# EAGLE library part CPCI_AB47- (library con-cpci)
Compact PCI A+B 47 Monoblock Source: www.erni.com
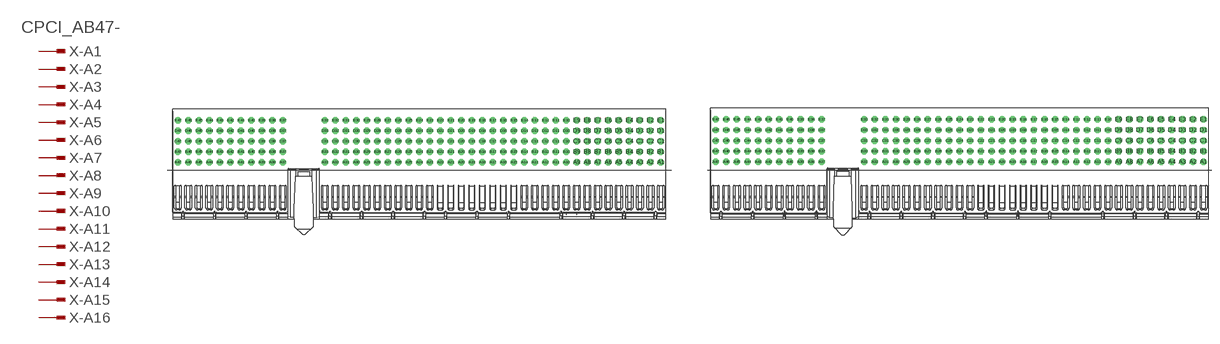
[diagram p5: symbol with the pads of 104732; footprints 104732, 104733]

Designator prefix X; gates -A1=PINV -A2=PIN -A3=PIN -A4=PIN -A5=PIN -A6=PIN -A7=PIN -A8=PIN -A9=PIN -A10=PIN -A11=PIN -A12=PIN -A13=PIN -A14=PIN -A15=PIN -A16=PIN -A17=PIN -A18=PIN -A19=PIN -A20=PIN -A21=PIN -A22=PIN -A23=PIN -A24=PIN -A25=PIN -A26=PIN -A27=PIN -A28=PIN -A29=PIN -A30=PIN -A31=PIN -A32=PIN -A33=PIN -A37=PIN -A38=PIN -A39=PIN -A40=PIN -A41=PIN -A42=PIN -A43=PIN -A44=PIN -A45=PIN -A46=PIN -A47=PIN -B1=PINV -C1=PINV -D1=PINV -E1=PINV -B2=PIN -B3=PIN -B4=PIN -B5=PIN -B6=PIN -B7=PIN -B8=PIN -B9=PIN -B10=PIN -B11=PIN -B12=PIN -B13=PIN -B14=PIN -B15=PIN -B16=PIN -B17=PIN -B18=PIN -B19=PIN -B20=PIN -B21=PIN -B22=PIN -B23=PIN -B24=PIN -B25=PIN -B26=PIN -B27=PIN -B28=PIN -B29=PIN -B30=PIN -B31=PIN -B32=PIN -B33=PIN -B37=PIN -B38=PIN -B39=PIN -B40=PIN -B41=PIN -B42=PIN -B43=PIN -B44=PIN -B45=PIN -B46=PIN -B47=PIN -C2=PIN -C3=PIN -C4=PIN -C5=PIN -C6=PIN -C7=PIN -C8=PIN -C9=PIN -C10=PIN -C11=PIN -C12=PIN -C13=PIN -C14=PIN -C15=PIN -C16=PIN -C17=PIN -C18=PIN -C19=PIN -C20=PIN -C21=PIN -C22=PIN -C23=PIN -C24=PIN -C25=PIN -C26=PIN -C27=PIN -C28=PIN -C29=PIN -C30=PIN -C31=PIN -C32=PIN -C33=PIN -C37=PIN -C38=PIN -C39=PIN -C40=PIN -C41=PIN -C42=PIN -C43=PIN -C44=PIN -C45=PIN -C46=PIN -C47=PIN -D2=PIN -D3=PIN -D4=PIN -D5=PIN -D6=PIN -D7=PIN -D8=PIN -D9=PIN -D10=PIN -D11=PIN -D12=PIN -D13=PIN -D14=PIN -D15=PIN -D16=PIN -D17=PIN -D18=PIN -D19=PIN -D20=PIN -D21=PIN -D22=PIN -D23=PIN -D24=PIN -D25=PIN -D26=PIN -D27=PIN -D28=PIN -D29=PIN -D30=PIN -D31=PIN -D32=PIN -D33=PIN -D37=PIN -D38=PIN -D39=PIN -D40=PIN -D41=PIN -D42=PIN -D43=PIN -D44=PIN -D45=PIN -D46=PIN -D47=PIN -E2=PIN -E3=PIN -E4=PIN -E5=PIN -E6=PIN -E7=PIN -E8=PIN -E9=PIN -E10=PIN -E11=PIN -E12=PIN -E13=PIN -E14=PIN -E15=PIN -E16=PIN -E17=PIN -E18=PIN -E19=PIN -E20=PIN -E21=PIN -E22=PIN -E23=PIN -E24=PIN -E25=PIN -E26=PIN -E27=PIN -E28=PIN -E29=PIN -E30=PIN -E31=PIN -E32=PIN -E33=PIN -E37=PIN -E38=PIN -E39=PIN -E40=PIN -E41=PIN -E42=PIN -E43=PIN -E44=PIN -E45=PIN -E46=PIN -E47=PIN

## CPCI_AB47-104732  [104732]
A1  -A1:1  in
A2  -A2:1  in
A3  -A3:1  in
A4  -A4:1  in
A5  -A5:1  in
A6  -A6:1  in
A7  -A7:1  in
A8  -A8:1  in
A9  -A9:1  in
A10  -A10:1  in
A11  -A11:1  in
A12  -A12:1  in
A13  -A13:1  in
A14  -A14:1  in
A15  -A15:1  in
A16  -A16:1  in
A17  -A17:1  in
A18  -A18:1  in
A19  -A19:1  in
A20  -A20:1  in
A21  -A21:1  in
A22  -A22:1  in
A23  -A23:1  in
A24  -A24:1  in
A25  -A25:1  in
A26  -A26:1  in
A27  -A27:1  in
A28  -A28:1  in
A29  -A29:1  in
A30  -A30:1  in
A31  -A31:1  in
A32  -A32:1  in
A33  -A33:1  in
A37  -A37:1  in
A38  -A38:1  in
A39  -A39:1  in
A40  -A40:1  in
A41  -A41:1  in
A42  -A42:1  in
A43  -A43:1  in
A44  -A44:1  in
A45  -A45:1  in
A46  -A46:1  in
A47  -A47:1  in
B1  -B1:1  in
B2  -B2:1  in
B3  -B3:1  in
B4  -B4:1  in
B5  -B5:1  in
B6  -B6:1  in
B7  -B7:1  in
B8  -B8:1  in
B9  -B9:1  in
B10  -B10:1  in
B11  -B11:1  in
B12  -B12:1  in
B13  -B13:1  in
B14  -B14:1  in
B15  -B15:1  in
B16  -B16:1  in
B17  -B17:1  in
B18  -B18:1  in
B19  -B19:1  in
B20  -B20:1  in
B21  -B21:1  in
B22  -B22:1  in
B23  -B23:1  in
B24  -B24:1  in
B25  -B25:1  in
B26  -B26:1  in
B27  -B27:1  in
B28  -B28:1  in
B29  -B29:1  in
B30  -B30:1  in
B31  -B31:1  in
B32  -B32:1  in
B33  -B33:1  in
B37  -B37:1  in
B38  -B38:1  in
B39  -B39:1  in
B40  -B40:1  in
B41  -B41:1  in
B42  -B42:1  in
B43  -B43:1  in
B44  -B44:1  in
B45  -B45:1  in
B46  -B46:1  in
B47  -B47:1  in
C1  -C1:1  in
C2  -C2:1  in
C3  -C3:1  in
C4  -C4:1  in
C5  -C5:1  in
C6  -C6:1  in
C7  -C7:1  in
C8  -C8:1  in
C9  -C9:1  in
C10  -C10:1  in
C11  -C11:1  in
C12  -C12:1  in
C13  -C13:1  in
C14  -C14:1  in
C15  -C15:1  in
C16  -C16:1  in
C17  -C17:1  in
C18  -C18:1  in
C19  -C19:1  in
C20  -C20:1  in
C21  -C21:1  in
C22  -C22:1  in
C23  -C23:1  in
C24  -C24:1  in
C25  -C25:1  in
C26  -C26:1  in
C27  -C27:1  in
C28  -C28:1  in
C29  -C29:1  in
C30  -C30:1  in
C31  -C31:1  in
C32  -C32:1  in
C33  -C33:1  in
C37  -C37:1  in
C38  -C38:1  in
C39  -C39:1  in
C40  -C40:1  in
C41  -C41:1  in
C42  -C42:1  in
C43  -C43:1  in
C44  -C44:1  in
C45  -C45:1  in
C46  -C46:1  in
C47  -C47:1  in
D1  -D1:1  in
D2  -D2:1  in
D3  -D3:1  in
D4  -D4:1  in
D5  -D5:1  in
D6  -D6:1  in
D7  -D7:1  in
D8  -D8:1  in
D9  -D9:1  in
D10  -D10:1  in
D11  -D11:1  in
D12  -D12:1  in
D13  -D13:1  in
D14  -D14:1  in
D15  -D15:1  in
D16  -D16:1  in
D17  -D17:1  in
D18  -D18:1  in
D19  -D19:1  in
D20  -D20:1  in
D21  -D21:1  in
D22  -D22:1  in
D23  -D23:1  in
D24  -D24:1  in
D25  -D25:1  in
D26  -D26:1  in
D27  -D27:1  in
D28  -D28:1  in
D29  -D29:1  in
D30  -D30:1  in
D31  -D31:1  in
D32  -D32:1  in
D33  -D33:1  in
D37  -D37:1  in
D38  -D38:1  in
D39  -D39:1  in
D40  -D40:1  in
D41  -D41:1  in
D42  -D42:1  in
D43  -D43:1  in
D44  -D44:1  in
D45  -D45:1  in
D46  -D46:1  in
D47  -D47:1  in
E1  -E1:1  in
E2  -E2:1  in
E3  -E3:1  in
E4  -E4:1  in
E5  -E5:1  in
E6  -E6:1  in
E7  -E7:1  in
E8  -E8:1  in
E9  -E9:1  in
E10  -E10:1  in
E11  -E11:1  in
E12  -E12:1  in
E13  -E13:1  in
E14  -E14:1  in
E15  -E15:1  in
E16  -E16:1  in
E17  -E17:1  in
E18  -E18:1  in
E19  -E19:1  in
E20  -E20:1  in
E21  -E21:1  in
E22  -E22:1  in
E23  -E23:1  in
E24  -E24:1  in
E25  -E25:1  in
E26  -E26:1  in
E27  -E27:1  in
E28  -E28:1  in
E29  -E29:1  in
E30  -E30:1  in
E31  -E31:1  in
E32  -E32:1  in
E33  -E33:1  in
E37  -E37:1  in
E38  -E38:1  in
E39  -E39:1  in
E40  -E40:1  in
E41  -E41:1  in
E42  -E42:1  in
E43  -E43:1  in
E44  -E44:1  in
E45  -E45:1  in
E46  -E46:1  in
E47  -E47:1  in

## CPCI_AB47-104733  [104733]
Pads as for 104732

## CPCI_AB47-104734  [104734]
Pads as for 104732

## CPCI_AB47-6U_AB47  [CPCI_6U_AB47]
Pads as for 104732

## CPCI_AB47-3U_AB47  [CPCI_3U_AB47]
Pads as for 104732

## Footprint 104732 (pad centres in mm)
ERmet Federleiste A+B 47 Monoblock Source: http://www.erni.com/DB/PDF-Drawing/ERmet/104732.pdf
drill 0.7 pad 1.016 octagon: A1 46,1.5; A2 44,1.5; A3 42,1.5; A4 40,1.5; A5 38,1.5; A6 36,1.5; A7 34,1.5; A8 32,1.5; A9 30,1.5; A10 28,1.5; A11 26,1.5; A12 24,1.5; A13 22,1.5; A14 20,1.5; A15 18,1.5; A16 16,1.5; A17 14,1.5; A18 12,1.5; A19 10,1.5; A20 8,1.5; A21 6,1.5; A22 4,1.5; A23 2,1.5; A24 0,1.5; A25 -2,1.5; A26 -4,1.5; A27 -6,1.5; A28 -8,1.5; A29 -10,1.5; A30 -12,1.5; A31 -14,1.5; A32 -16,1.5; A33 -18,1.5; A37 -26,1.5; A38 -28,1.5; A39 -30,1.5; A40 -32,1.5; A41 -34,1.5; A42 -36,1.5; A43 -38,1.5; A44 -40,1.5; A45 -42,1.5; A46 -44,1.5; A47 -46,1.5; B1 46,3.5; B2 44,3.5; B3 42,3.5; B4 40,3.5; B5 38,3.5; B6 36,3.5; B7 34,3.5; B8 32,3.5; B9 30,3.5; B10 28,3.5; B11 26,3.5; B12 24,3.5; B13 22,3.5; B14 20,3.5; B15 18,3.5; B16 16,3.5; B17 14,3.5; B18 12,3.5; B19 10,3.5; B20 8,3.5; B21 6,3.5; B22 4,3.5; B23 2,3.5; B24 0,3.5; B25 -2,3.5; B26 -4,3.5; B27 -6,3.5; B28 -8,3.5; B29 -10,3.5; B30 -12,3.5; B31 -14,3.5; B32 -16,3.5; B33 -18,3.5; B37 -26,3.5; B38 -28,3.5; B39 -30,3.5; B40 -32,3.5; B41 -34,3.5; B42 -36,3.5; B43 -38,3.5; B44 -40,3.5; B45 -42,3.5; B46 -44,3.5; B47 -46,3.5; C1 46,5.5; C2 44,5.5; C3 42,5.5; C4 40,5.5; C5 38,5.5; C6 36,5.5; C7 34,5.5; C8 32,5.5; C9 30,5.5; C10 28,5.5; C11 26,5.5; C12 24,5.5; C13 22,5.5; C14 20,5.5; C15 18,5.5; C16 16,5.5; C17 14,5.5; C18 12,5.5; C19 10,5.5; C20 8,5.5; C21 6,5.5; C22 4,5.5; C23 2,5.5; C24 0,5.5; C25 -2,5.5; C26 -4,5.5; C27 -6,5.5; C28 -8,5.5; C29 -10,5.5; C30 -12,5.5; C31 -14,5.5; C32 -16,5.5; C33 -18,5.5; C37 -26,5.5; C38 -28,5.5; C39 -30,5.5; C40 -32,5.5; C41 -34,5.5; C42 -36,5.5; C43 -38,5.5; C44 -40,5.5; C45 -42,5.5; C46 -44,5.5; C47 -46,5.5; D1 46,7.5; D2 44,7.5; D3 42,7.5; D4 40,7.5; D5 38,7.5; D6 36,7.5; D7 34,7.5; D8 32,7.5; D9 30,7.5; D10 28,7.5; D11 26,7.5; D12 24,7.5; D13 22,7.5; D14 20,7.5; D15 18,7.5; D16 16,7.5; D17 14,7.5; D18 12,7.5; D19 10,7.5; D20 8,7.5; D21 6,7.5; D22 4,7.5; D23 2,7.5; D24 0,7.5; D25 -2,7.5; D26 -4,7.5; D27 -6,7.5; D28 -8,7.5; D29 -10,7.5; D30 -12,7.5; D31 -14,7.5; D32 -16,7.5; D33 -18,7.5; D37 -26,7.5; D38 -28,7.5; D39 -30,7.5; D40 -32,7.5; D41 -34,7.5; D42 -36,7.5; D43 -38,7.5; D44 -40,7.5; D45 -42,7.5; D46 -44,7.5; D47 -46,7.5; E1 46,9.5; E2 44,9.5; E3 42,9.5; E4 40,9.5; E5 38,9.5; E6 36,9.5; E7 34,9.5; E8 32,9.5; E9 30,9.5; E10 28,9.5; E11 26,9.5; E12 24,9.5; E13 22,9.5; E14 20,9.5; E15 18,9.5; E16 16,9.5; E17 14,9.5; E18 12,9.5; E19 10,9.5; E20 8,9.5; E21 6,9.5; E22 4,9.5; E23 2,9.5; E24 0,9.5; E25 -2,9.5; E26 -4,9.5; E27 -6,9.5; E28 -8,9.5; E29 -10,9.5; E30 -12,9.5; E31 -14,9.5; E32 -16,9.5; E33 -18,9.5; E37 -26,9.5; E38 -28,9.5; E39 -30,9.5; E40 -32,9.5; E41 -34,9.5; E42 -36,9.5; E43 -38,9.5; E44 -40,9.5; E45 -42,9.5; E46 -44,9.5; E47 -46,9.5

## Footprint 104733 (pad centres in mm)
ERmet Federleiste A+B 47 Monoblock 3.3V/gelb Source: http://www.erni.com/DB/PDF-Drawing/ERmet/104733.pdf
drill 0.7 pad 1.016 octagon: A1 46,1.5; A2 44,1.5; A3 42,1.5; A4 40,1.5; A5 38,1.5; A6 36,1.5; A7 34,1.5; A8 32,1.5; A9 30,1.5; A10 28,1.5; A11 26,1.5; A12 24,1.5; A13 22,1.5; A14 20,1.5; A15 18,1.5; A16 16,1.5; A17 14,1.5; A18 12,1.5; A19 10,1.5; A20 8,1.5; A21 6,1.5; A22 4,1.5; A23 2,1.5; A24 0,1.5; A25 -2,1.5; A26 -4,1.5; A27 -6,1.5; A28 -8,1.5; A29 -10,1.5; A30 -12,1.5; A31 -14,1.5; A32 -16,1.5; A33 -18,1.5; A37 -26,1.5; A38 -28,1.5; A39 -30,1.5; A40 -32,1.5; A41 -34,1.5; A42 -36,1.5; A43 -38,1.5; A44 -40,1.5; A45 -42,1.5; A46 -44,1.5; A47 -46,1.5; B1 46,3.5; B2 44,3.5; B3 42,3.5; B4 40,3.5; B5 38,3.5; B6 36,3.5; B7 34,3.5; B8 32,3.5; B9 30,3.5; B10 28,3.5; B11 26,3.5; B12 24,3.5; B13 22,3.5; B14 20,3.5; B15 18,3.5; B16 16,3.5; B17 14,3.5; B18 12,3.5; B19 10,3.5; B20 8,3.5; B21 6,3.5; B22 4,3.5; B23 2,3.5; B24 0,3.5; B25 -2,3.5; B26 -4,3.5; B27 -6,3.5; B28 -8,3.5; B29 -10,3.5; B30 -12,3.5; B31 -14,3.5; B32 -16,3.5; B33 -18,3.5; B37 -26,3.5; B38 -28,3.5; B39 -30,3.5; B40 -32,3.5; B41 -34,3.5; B42 -36,3.5; B43 -38,3.5; B44 -40,3.5; B45 -42,3.5; B46 -44,3.5; B47 -46,3.5; C1 46,5.5; C2 44,5.5; C3 42,5.5; C4 40,5.5; C5 38,5.5; C6 36,5.5; C7 34,5.5; C8 32,5.5; C9 30,5.5; C10 28,5.5; C11 26,5.5; C12 24,5.5; C13 22,5.5; C14 20,5.5; C15 18,5.5; C16 16,5.5; C17 14,5.5; C18 12,5.5; C19 10,5.5; C20 8,5.5; C21 6,5.5; C22 4,5.5; C23 2,5.5; C24 0,5.5; C25 -2,5.5; C26 -4,5.5; C27 -6,5.5; C28 -8,5.5; C29 -10,5.5; C30 -12,5.5; C31 -14,5.5; C32 -16,5.5; C33 -18,5.5; C37 -26,5.5; C38 -28,5.5; C39 -30,5.5; C40 -32,5.5; C41 -34,5.5; C42 -36,5.5; C43 -38,5.5; C44 -40,5.5; C45 -42,5.5; C46 -44,5.5; C47 -46,5.5; D1 46,7.5; D2 44,7.5; D3 42,7.5; D4 40,7.5; D5 38,7.5; D6 36,7.5; D7 34,7.5; D8 32,7.5; D9 30,7.5; D10 28,7.5; D11 26,7.5; D12 24,7.5; D13 22,7.5; D14 20,7.5; D15 18,7.5; D16 16,7.5; D17 14,7.5; D18 12,7.5; D19 10,7.5; D20 8,7.5; D21 6,7.5; D22 4,7.5; D23 2,7.5; D24 0,7.5; D25 -2,7.5; D26 -4,7.5; D27 -6,7.5; D28 -8,7.5; D29 -10,7.5; D30 -12,7.5; D31 -14,7.5; D32 -16,7.5; D33 -18,7.5; D37 -26,7.5; D38 -28,7.5; D39 -30,7.5; D40 -32,7.5; D41 -34,7.5; D42 -36,7.5; D43 -38,7.5; D44 -40,7.5; D45 -42,7.5; D46 -44,7.5; D47 -46,7.5; E1 46,9.5; E2 44,9.5; E3 42,9.5; E4 40,9.5; E5 38,9.5; E6 36,9.5; E7 34,9.5; E8 32,9.5; E9 30,9.5; E10 28,9.5; E11 26,9.5; E12 24,9.5; E13 22,9.5; E14 20,9.5; E15 18,9.5; E16 16,9.5; E17 14,9.5; E18 12,9.5; E19 10,9.5; E20 8,9.5; E21 6,9.5; E22 4,9.5; E23 2,9.5; E24 0,9.5; E25 -2,9.5; E26 -4,9.5; E27 -6,9.5; E28 -8,9.5; E29 -10,9.5; E30 -12,9.5; E31 -14,9.5; E32 -16,9.5; E33 -18,9.5; E37 -26,9.5; E38 -28,9.5; E39 -30,9.5; E40 -32,9.5; E41 -34,9.5; E42 -36,9.5; E43 -38,9.5; E44 -40,9.5; E45 -42,9.5; E46 -44,9.5; E47 -46,9.5

## Footprint 104734 (pad centres in mm)
ERmet Federleiste A+B 47 Monoblock 5V/blau Source: http://www.erni.com/DB/PDF-Drawing/ERmet/104734.pdf
drill 0.7 pad 1.016 octagon: A1 46,1.5; A2 44,1.5; A3 42,1.5; A4 40,1.5; A5 38,1.5; A6 36,1.5; A7 34,1.5; A8 32,1.5; A9 30,1.5; A10 28,1.5; A11 26,1.5; A12 24,1.5; A13 22,1.5; A14 20,1.5; A15 18,1.5; A16 16,1.5; A17 14,1.5; A18 12,1.5; A19 10,1.5; A20 8,1.5; A21 6,1.5; A22 4,1.5; A23 2,1.5; A24 0,1.5; A25 -2,1.5; A26 -4,1.5; A27 -6,1.5; A28 -8,1.5; A29 -10,1.5; A30 -12,1.5; A31 -14,1.5; A32 -16,1.5; A33 -18,1.5; A37 -26,1.5; A38 -28,1.5; A39 -30,1.5; A40 -32,1.5; A41 -34,1.5; A42 -36,1.5; A43 -38,1.5; A44 -40,1.5; A45 -42,1.5; A46 -44,1.5; A47 -46,1.5; B1 46,3.5; B2 44,3.5; B3 42,3.5; B4 40,3.5; B5 38,3.5; B6 36,3.5; B7 34,3.5; B8 32,3.5; B9 30,3.5; B10 28,3.5; B11 26,3.5; B12 24,3.5; B13 22,3.5; B14 20,3.5; B15 18,3.5; B16 16,3.5; B17 14,3.5; B18 12,3.5; B19 10,3.5; B20 8,3.5; B21 6,3.5; B22 4,3.5; B23 2,3.5; B24 0,3.5; B25 -2,3.5; B26 -4,3.5; B27 -6,3.5; B28 -8,3.5; B29 -10,3.5; B30 -12,3.5; B31 -14,3.5; B32 -16,3.5; B33 -18,3.5; B37 -26,3.5; B38 -28,3.5; B39 -30,3.5; B40 -32,3.5; B41 -34,3.5; B42 -36,3.5; B43 -38,3.5; B44 -40,3.5; B45 -42,3.5; B46 -44,3.5; B47 -46,3.5; C1 46,5.5; C2 44,5.5; C3 42,5.5; C4 40,5.5; C5 38,5.5; C6 36,5.5; C7 34,5.5; C8 32,5.5; C9 30,5.5; C10 28,5.5; C11 26,5.5; C12 24,5.5; C13 22,5.5; C14 20,5.5; C15 18,5.5; C16 16,5.5; C17 14,5.5; C18 12,5.5; C19 10,5.5; C20 8,5.5; C21 6,5.5; C22 4,5.5; C23 2,5.5; C24 0,5.5; C25 -2,5.5; C26 -4,5.5; C27 -6,5.5; C28 -8,5.5; C29 -10,5.5; C30 -12,5.5; C31 -14,5.5; C32 -16,5.5; C33 -18,5.5; C37 -26,5.5; C38 -28,5.5; C39 -30,5.5; C40 -32,5.5; C41 -34,5.5; C42 -36,5.5; C43 -38,5.5; C44 -40,5.5; C45 -42,5.5; C46 -44,5.5; C47 -46,5.5; D1 46,7.5; D2 44,7.5; D3 42,7.5; D4 40,7.5; D5 38,7.5; D6 36,7.5; D7 34,7.5; D8 32,7.5; D9 30,7.5; D10 28,7.5; D11 26,7.5; D12 24,7.5; D13 22,7.5; D14 20,7.5; D15 18,7.5; D16 16,7.5; D17 14,7.5; D18 12,7.5; D19 10,7.5; D20 8,7.5; D21 6,7.5; D22 4,7.5; D23 2,7.5; D24 0,7.5; D25 -2,7.5; D26 -4,7.5; D27 -6,7.5; D28 -8,7.5; D29 -10,7.5; D30 -12,7.5; D31 -14,7.5; D32 -16,7.5; D33 -18,7.5; D37 -26,7.5; D38 -28,7.5; D39 -30,7.5; D40 -32,7.5; D41 -34,7.5; D42 -36,7.5; D43 -38,7.5; D44 -40,7.5; D45 -42,7.5; D46 -44,7.5; D47 -46,7.5; E1 46,9.5; E2 44,9.5; E3 42,9.5; E4 40,9.5; E5 38,9.5; E6 36,9.5; E7 34,9.5; E8 32,9.5; E9 30,9.5; E10 28,9.5; E11 26,9.5; E12 24,9.5; E13 22,9.5; E14 20,9.5; E15 18,9.5; E16 16,9.5; E17 14,9.5; E18 12,9.5; E19 10,9.5; E20 8,9.5; E21 6,9.5; E22 4,9.5; E23 2,9.5; E24 0,9.5; E25 -2,9.5; E26 -4,9.5; E27 -6,9.5; E28 -8,9.5; E29 -10,9.5; E30 -12,9.5; E31 -14,9.5; E32 -16,9.5; E33 -18,9.5; E37 -26,9.5; E38 -28,9.5; E39 -30,9.5; E40 -32,9.5; E41 -34,9.5; E42 -36,9.5; E43 -38,9.5; E44 -40,9.5; E45 -42,9.5; E46 -44,9.5; E47 -46,9.5

## Footprint CPCI_6U_AB47 (pad centres in mm)
Compact PCI Shortform Specification November 1, 1995 Source: http://www.picmg.org/test/pdf/cpcispec.pdf
drill 0.7 pad 1.016 octagon: A1 158.5,96; A2 158.5,94; A3 158.5,92; A4 158.5,90; A5 158.5,88; A6 158.5,86; A7 158.5,84; A8 158.5,82; A9 158.5,80; A10 158.5,78; A11 158.5,76; A12 158.5,74; A13 158.5,72; A14 158.5,70; A15 158.5,68; A16 158.5,66; A17 158.5,64; A18 158.5,62; A19 158.5,60; A20 158.5,58; A21 158.5,56; A22 158.5,54; A23 158.5,52; A24 158.5,50; A25 158.5,48; A26 158.5,46; A27 158.5,44; A28 158.5,42; A29 158.5,40; A30 158.5,38; A31 158.5,36; A32 158.5,34; A33 158.5,32; A37 158.5,24; A38 158.5,22; A39 158.5,20; A40 158.5,18; A41 158.5,16; A42 158.5,14; A43 158.5,12; A44 158.5,10; A45 158.5,8; A46 158.5,6; A47 158.5,4; B1 156.5,96; B2 156.5,94; B3 156.5,92; B4 156.5,90; B5 156.5,88; B6 156.5,86; B7 156.5,84; B8 156.5,82; B9 156.5,80; B10 156.5,78; B11 156.5,76; B12 156.5,74; B13 156.5,72; B14 156.5,70; B15 156.5,68; B16 156.5,66; B17 156.5,64; B18 156.5,62; B19 156.5,60; B20 156.5,58; B21 156.5,56; B22 156.5,54; B23 156.5,52; B24 156.5,50; B25 156.5,48; B26 156.5,46; B27 156.5,44; B28 156.5,42; B29 156.5,40; B30 156.5,38; B31 156.5,36; B32 156.5,34; B33 156.5,32; B37 156.5,24; B38 156.5,22; B39 156.5,20; B40 156.5,18; B41 156.5,16; B42 156.5,14; B43 156.5,12; B44 156.5,10; B45 156.5,8; B46 156.5,6; B47 156.5,4; C1 154.5,96; C2 154.5,94; C3 154.5,92; C4 154.5,90; C5 154.5,88; C6 154.5,86; C7 154.5,84; C8 154.5,82; C9 154.5,80; C10 154.5,78; C11 154.5,76; C12 154.5,74; C13 154.5,72; C14 154.5,70; C15 154.5,68; C16 154.5,66; C17 154.5,64; C18 154.5,62; C19 154.5,60; C20 154.5,58; C21 154.5,56; C22 154.5,54; C23 154.5,52; C24 154.5,50; C25 154.5,48; C26 154.5,46; C27 154.5,44; C28 154.5,42; C29 154.5,40; C30 154.5,38; C31 154.5,36; C32 154.5,34; C33 154.5,32; C37 154.5,24; C38 154.5,22; C39 154.5,20; C40 154.5,18; C41 154.5,16; C42 154.5,14; C43 154.5,12; C44 154.5,10; C45 154.5,8; C46 154.5,6; C47 154.5,4; D1 152.5,96; D2 152.5,94; D3 152.5,92; D4 152.5,90; D5 152.5,88; D6 152.5,86; D7 152.5,84; D8 152.5,82; D9 152.5,80; D10 152.5,78; D11 152.5,76; D12 152.5,74; D13 152.5,72; D14 152.5,70; D15 152.5,68; D16 152.5,66; D17 152.5,64; D18 152.5,62; D19 152.5,60; D20 152.5,58; D21 152.5,56; D22 152.5,54; D23 152.5,52; D24 152.5,50; D25 152.5,48; D26 152.5,46; D27 152.5,44; D28 152.5,42; D29 152.5,40; D30 152.5,38; D31 152.5,36; D32 152.5,34; D33 152.5,32; D37 152.5,24; D38 152.5,22; D39 152.5,20; D40 152.5,18; D41 152.5,16; D42 152.5,14; D43 152.5,12; D44 152.5,10; D45 152.5,8; D46 152.5,6; D47 152.5,4; E1 150.5,96; E2 150.5,94; E3 150.5,92; E4 150.5,90; E5 150.5,88; E6 150.5,86; E7 150.5,84; E8 150.5,82; E9 150.5,80; E10 150.5,78; E11 150.5,76; E12 150.5,74; E13 150.5,72; E14 150.5,70; E15 150.5,68; E16 150.5,66; E17 150.5,64; E18 150.5,62; E19 150.5,60; E20 150.5,58; E21 150.5,56; E22 150.5,54; E23 150.5,52; E24 150.5,50; E25 150.5,48; E26 150.5,46; E27 150.5,44; E28 150.5,42; E29 150.5,40; E30 150.5,38; E31 150.5,36; E32 150.5,34; E33 150.5,32; E37 150.5,24; E38 150.5,22; E39 150.5,20; E40 150.5,18; E41 150.5,16; E42 150.5,14; E43 150.5,12; E44 150.5,10; E45 150.5,8; E46 150.5,6; E47 150.5,4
